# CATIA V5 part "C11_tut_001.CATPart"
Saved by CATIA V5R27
Part number: Part1
Bounding box of the stored display mesh (mm): x -74.488 to 0, y -50 to 50, z -100 to 0
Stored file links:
  E:\_Deepak\2017_Deepak\CATIA\Resources\Tutorial Files\Tutorials\c11_catia_v5_6r2016_tut\C11_tut_001.CATPart
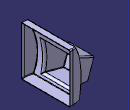
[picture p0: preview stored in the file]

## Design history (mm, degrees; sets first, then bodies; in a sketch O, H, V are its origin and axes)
Body1 (main body)
  Sketch1 on zx-plane, origin (0, 0, 0), H (-1, 0, 0), V (0, 0, 1)
    line L1 (0, 0) -> (12, 0)
    arc A1 centre (-96.8872, -61.3887) radius 125 from (12, 0) to (22, -100) cw
    line L2 (22, -100) -> (0, -100)
    point P4 (0, -100)
    length L1 = 12
    length L2 = 22
    distance L1 L2 = 100
    radius A1 = 125
    horizontal: L1 H, L2 H
    coincidence: P4 V
  Extrude1: Element1 Sketch1, Lim1 50, Lim2 50
  Sketch2 on zx-plane, origin (0, 0, 0), H (-1, 0, 0), V (0, 0, 1)
    line L1 (20, -40) -> (74.9495, -60)
    point P1 (20, -40)
    point P2 (74.9495, -60)
    reference projected line E1 (22, -100) -> (0, -100) from edge of Extrude1
    distance P2 H = 60
    distance P1 E1 = 60
    distance V P1 = 20
    angle L1 H = 20
  Plane1: type Normal, Curve Sketch2, RefPoint Sketch2.P2, Ratio 0
  Sketch3 on Plane1, origin (-85.4657, 0, -31.107), H (0, -1, 0), V (-0.342, 0, 0.9397)
    point P1 (-25, -30.7473)
    line L1 (-25, -30.7473) -> (25, -30.7473)
    line L2 (25, -30.7473) -> (25, -70.7473)
    line L3 (25, -70.7473) -> (-25, -70.7473)
    line L4 (-25, -70.7473) -> (-25, -30.7473)
    point P2 (25, -30.7473)
    reference projected point E1 (0, -30.7473) from Sketch2.P2
    axis line L5 (0, 21.6916) -> (0, -100.0328)
    point P5 (0, 21.6916)
    length L3 = 50
    length L2 = 40
    horizontal: L1 H, L3 H
    vertical: L2 V, L4 V, L5 V
    coincidence: L1 E1, P5 V
    symmetry: P1 P2 L5
  Plane2: type Normal, Curve Sketch2, RefPoint Sketch2.P1, Ratio 0
  Sketch4 on Plane2, origin (-30.5162, 0, -11.107), H (0, -1, 0), V (-0.342, 0, 0.9397)
    line L1 (-32.5, -21.2473) -> (32.5, -21.2473)
    line L2 (32.5, -21.2473) -> (32.5, -81.2473)
    line L3 (32.5, -81.2473) -> (-32.5, -81.2473)
    line L4 (-32.5, -81.2473) -> (-32.5, -21.2473)
    reference projected line E1 (25, -30.7473) -> (-25, -30.7473) from Sketch3.L1
    distance E1 L1 = 9.5
    distance V L2 = 32.5
    length L3 = 65
    length L2 = 60
    horizontal: L1 H, L3 H
    vertical: L2 V, L4 V
  Loft1: Sections (Sketch3; Sketch4), SectionCouplingPoints ({coupling CouplingPoints (vertex [element of Sketch3 | element of Sketch3]; vertex [element of Sketch4 | element of Sketch4])}; {coupling CouplingPoints (vertex [element of Sketch3 | element of Sketch3]; vertex [element of Sketch4 | element of Sketch4])}; {coupling CouplingPoints (vertex [element of Sketch3 | element of Sketch3]; vertex [element of Sketch4 | element of Sketch4])}; {coupling CouplingPoints (vertex [element of Sketch3 | element of Sketch3]; vertex [element of Sketch4 | element of Sketch4])})
  Sketch5 on face of Extrude1 from Sketch1.L1, origin (0, 0, 0), H (1, 0, 0), V (0, -1, 0)
    point P1 (0, -50)
    line L1 (0, -50) -> (-5, -50)
    reference projected point E1 (0, -50) from vertex [face of Extrude1 from Sketch1.L2]
    arc A1 centre (-5, 0) radius 50 from (-5, -50) to (-35.922, -39.2916) cw
    length L1 = 5
    radius A1 = 50
    horizontal: L1 H
    coincidence: P1 E1
    tangency: A1 L1
  Extrude2: Element1 Sketch5, Lim1 100, Lim2 0
  Symmetry1: ToTransfor Extrude2, Reference zx-plane
  Trim1: Trimmed (Extrude2; Extrude1)
  Trim2: Trimmed (Trim1; Symmetry1)
  Trim3: Trimmed (Loft1; Trim2)
  CloseSurface1: CloseElement Trim3
  Sketch6 on face of CloseSurface1, origin (-85.4657, 0, -31.107), H (0, -1, 0), V (-0.342, 0, 0.9397)
    line L1 (-20, -55.7473) -> (0, -55.7473)
    line L2 (0, -55.7473) -> (0, -65.7473)
    line L3 (0, -65.7473) -> (-20, -65.7473)
    line L4 (-20, -65.7473) -> (-20, -55.7473)
    reference projected line E1 (-25, -70.7473) -> (25, -70.7473) from edge [face of CloseSurface1 | face of CloseSurface1]
    reference projected line E2 (-25, -30.7473) -> (-25, -70.7473) from edge [face of CloseSurface1 | face of CloseSurface1]
    length L1 = 20
    length L4 = 10
    distance L3 E1 = 5
    distance L4 E2 = 5
    horizontal: L1 H, L3 H
    vertical: L2 V, L4 V
  Pocket1: profile Sketch6, direction (0.9397, 0, 0.342), length 5
  Fillet1: radius 1, on edge [face of CloseSurface1 | face of Pocket1 from Sketch6.L1]; edge [face of CloseSurface1 | face of Pocket1 from Sketch6.L2]; edge [face of CloseSurface1 | face of Pocket1 from Sketch6.L3]; edge [face of CloseSurface1 | face of Pocket1 from Sketch6.L4]; face of Pocket1 from Sketch6.L1; edge [face of Pocket1 from Sketch6.L1 | face of Pocket1 from Sketch6.L2]; edge [face of Pocket1 from Sketch6.L2 | end face of Pocket1]; edge [face of Pocket1 from Sketch6.L2 | face of Pocket1 from Sketch6.L3]; edge [face of Pocket1 from Sketch6.L3 | end face of Pocket1]; edge [face of Pocket1 from Sketch6.L3 | face of Pocket1 from Sketch6.L4]; edge [face of Pocket1 from Sketch6.L4 | end face of Pocket1]
  Fillet2: radius 3.5, on edge [face of CloseSurface1 | face of CloseSurface1] (x4)
  Fillet3: radius 2, on edge [face of CloseSurface1 | face of CloseSurface1] (x12)
  Fillet4: radius 2, on edge [face of CloseSurface1 | face of CloseSurface1] (x5); edge [face of CloseSurface1 | face of Fillet3]
  Shell1: ExtOffset 0, Face face of CloseSurface1, IntOffset 1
